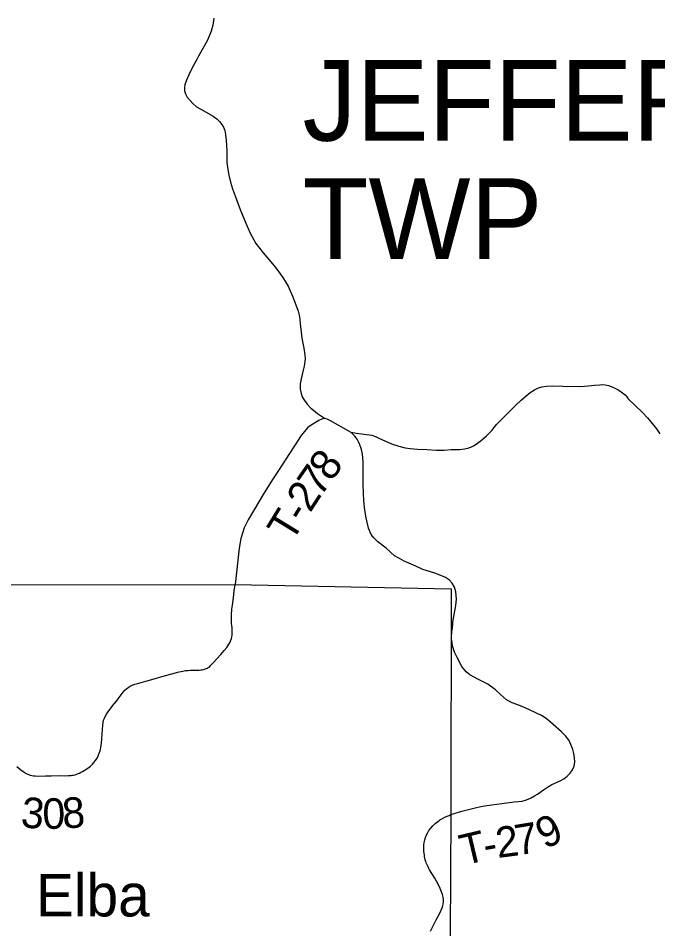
# Model space of a CAD drawing. Extents: x -10.5 to 40.6, y -3.2 to 22.
# Drawn here: x -9.045 to -7.857, y 17.758 to 19.45 of the extents above; entities that cross this region are included whole.
import ezdxf

# ---------------------------------------------------------------- set-up
doc = ezdxf.new("R2010")
doc.units = 0
for name, color, linetype in [('GM_X_Township_Road', 7, 'Continuous'), ('GM_X_Township_Road_Text', 7, 'Continuous'), ('GM_X_Township_Text', 7, 'Continuous'), ('GM_X_Unincorporated_Text', 7, 'Continuous')]:
    doc.layers.add(name, color=color, linetype=linetype)

msp = doc.modelspace()

# ---------------------------------------------------------------- linework, layer by layer
at = {"layer": 'GM_X_Township_Road'}
for points in [[(-8.6812, 19.45), (-8.6832, 19.4369), (-8.6862, 19.4259), (-8.6897, 19.4164), (-8.6939, 19.4076), (-8.7095, 19.3795), (-8.7125, 19.3745), (-8.7227, 19.3552), (-8.728, 19.3443), (-8.7323, 19.3345), (-8.735, 19.3258), (-8.7357, 19.3209), (-8.7357, 19.3151), (-8.734, 19.3092), (-8.7307, 19.3032), (-8.7252, 19.2969), (-8.7202, 19.2912), (-8.7134, 19.2854), (-8.7057, 19.2808), (-8.6823, 19.2675), (-8.6756, 19.2626), (-8.6705, 19.2577), (-8.6663, 19.2525), (-8.6633, 19.2474), (-8.6609, 19.2409), (-8.6594, 19.2337), (-8.6584, 19.223), (-8.6573, 19.203), (-8.657, 19.1814), (-8.6555, 19.1684), (-8.6537, 19.1583), (-8.6502, 19.1454), (-8.6465, 19.1327), (-8.6413, 19.118), (-8.6369, 19.1058), (-8.6325, 19.0943), (-8.622, 19.0687), (-8.6141, 19.0501), (-8.6031, 19.0313), (-8.5896, 19.0138), (-8.5721, 18.9933), (-8.5659, 18.986), (-8.5529, 18.9682), (-8.5435, 18.9519), (-8.5351, 18.9331), (-8.531, 18.9224), (-8.5246, 18.9051), (-8.5227, 18.8981), (-8.5214, 18.8902), (-8.5209, 18.8821), (-8.5194, 18.8661), (-8.5178, 18.8551), (-8.5141, 18.8364), (-8.5122, 18.8244), (-8.5119, 18.8168), (-8.5138, 18.8033), (-8.5155, 18.7958), (-8.5193, 18.7794), (-8.5207, 18.7702), (-8.5211, 18.7653), (-8.5212, 18.7605), (-8.5193, 18.7526), (-8.517, 18.7461), (-8.5129, 18.7394), (-8.5079, 18.7325), (-8.5012, 18.7254), (-8.4964, 18.7211), (-8.4887, 18.7154), (-8.4815, 18.7103), (-8.4756, 18.7067), (-8.4713, 18.705), (-8.465, 18.702), (-8.4266, 18.6803), (-8.4192, 18.679), (-8.4171, 18.6787)], [(-8.4171, 18.6787), (-8.4119, 18.6781), (-8.3979, 18.6762), (-8.3877, 18.6748), (-8.3814, 18.6724), (-8.3749, 18.6693), (-8.3516, 18.659), (-8.3376, 18.6542), (-8.3257, 18.6512), (-8.3167, 18.65), (-8.3034, 18.6491), (-8.2859, 18.6484), (-8.2677, 18.6468), (-8.2538, 18.647), (-8.2403, 18.648), (-8.2249, 18.6486), (-8.2157, 18.6496), (-8.2097, 18.6509), (-8.2039, 18.6528), (-8.1981, 18.656), (-8.1915, 18.6602), (-8.1844, 18.6658), (-8.175, 18.6737), (-8.1699, 18.6785), (-8.1648, 18.6839), (-8.1561, 18.6945), (-8.1473, 18.7039), (-8.1353, 18.716), (-8.1205, 18.7305), (-8.1104, 18.7399), (-8.1015, 18.748), (-8.0937, 18.7542), (-8.0859, 18.7591), (-8.0787, 18.7628), (-8.0713, 18.7648), (-8.0635, 18.7662), (-8.0521, 18.7669), (-8.0334, 18.7659), (-8.0003, 18.7653), (-7.9854, 18.7668), (-7.9745, 18.768), (-7.9642, 18.7687), (-7.959, 18.7691), (-7.9545, 18.7686), (-7.9487, 18.7671), (-7.9406, 18.7643), (-7.9341, 18.7611), (-7.929, 18.7584), (-7.9221, 18.7538), (-7.9175, 18.7497), (-7.9143, 18.7463), (-7.9116, 18.7425), (-7.8855, 18.7171), (-7.8762, 18.7074), (-7.8695, 18.6996), (-7.8593, 18.6868), (-7.8529, 18.6777)], [(-8.4756, 18.7067), (-8.4807, 18.7049), (-8.4861, 18.7022), (-8.5007, 18.6937), (-8.5065, 18.6893), (-8.5107, 18.6849), (-8.5193, 18.6745), (-8.5614, 18.6094), (-8.5711, 18.5947), (-8.588, 18.5678), (-8.6177, 18.5176), (-8.6247, 18.5029), (-8.6282, 18.4929), (-8.6309, 18.4831), (-8.6343, 18.4649), (-8.6419, 18.3972)], [(-8.2409, 17.9698), (-8.2208, 17.9762), (-8.1959, 17.9825), (-8.1852, 17.985), (-8.1743, 17.9867), (-8.1464, 17.9903), (-8.1234, 17.9933), (-8.1158, 17.994), (-8.1086, 17.9948), (-8.1009, 17.9971), (-8.0935, 18.0003), (-8.0859, 18.0045), (-8.0801, 18.008), (-8.0694, 18.0156), (-8.0617, 18.0206), (-8.0536, 18.0256), (-8.0382, 18.0327), (-8.0315, 18.0365), (-8.0251, 18.041), (-8.0194, 18.047), (-8.015, 18.0532), (-8.0123, 18.0601), (-8.011, 18.0679), (-8.0115, 18.0753), (-8.0127, 18.0831), (-8.0148, 18.0908), (-8.0169, 18.097), (-8.0216, 18.1077), (-8.0283, 18.116), (-8.0359, 18.1236), (-8.0511, 18.1374), (-8.0613, 18.1459), (-8.0662, 18.1497), (-8.0731, 18.1537), (-8.0823, 18.1586), (-8.0964, 18.1653), (-8.1118, 18.1718), (-8.1271, 18.1775), (-8.1376, 18.1832), (-8.1491, 18.1928), (-8.1584, 18.2017), (-8.1725, 18.2121), (-8.1908, 18.2212), (-8.2059, 18.2295), (-8.2128, 18.235), (-8.2206, 18.245), (-8.2297, 18.262), (-8.2343, 18.2716), (-8.2378, 18.2833), (-8.239, 18.2894), (-8.2395, 18.2926), (-8.2397, 18.2956), (-8.2398, 18.2987), (-8.2397, 18.3019), (-8.2395, 18.3058), (-8.2391, 18.3095), (-8.2388, 18.3132), (-8.2384, 18.317), (-8.2381, 18.3196), (-8.2377, 18.3222), (-8.2375, 18.3244), (-8.2372, 18.3266), (-8.2368, 18.3309), (-8.2322, 18.3584), (-8.2309, 18.3703), (-8.2317, 18.3837), (-8.2341, 18.3926), (-8.2386, 18.3999), (-8.2437, 18.4057), (-8.251, 18.4105), (-8.2595, 18.4143), (-8.271, 18.4182), (-8.2929, 18.4255), (-8.3063, 18.4314), (-8.3279, 18.4408), (-8.3366, 18.4456), (-8.3459, 18.4507), (-8.3615, 18.4648), (-8.3768, 18.4768), (-8.3845, 18.4839), (-8.3894, 18.4901), (-8.3944, 18.5023), (-8.3983, 18.5214), (-8.4009, 18.5354), (-8.4028, 18.5527), (-8.4039, 18.5825), (-8.4041, 18.6259), (-8.4053, 18.6396), (-8.4068, 18.648), (-8.4101, 18.6572), (-8.4124, 18.6625), (-8.4154, 18.6672), (-8.4193, 18.673), (-8.4223, 18.6764), (-8.4266, 18.6803)], [(-9.0472, 18.0594), (-9.0434, 18.0561), (-9.0397, 18.053), (-9.0336, 18.0484), (-9.0299, 18.0462), (-9.0266, 18.0447), (-9.0225, 18.0433), (-9.0195, 18.0425), (-9.0163, 18.042), (-9.0134, 18.0417), (-9.0072, 18.0415), (-8.9942, 18.0417), (-8.9837, 18.0419), (-8.9688, 18.0422), (-8.9588, 18.0421), (-8.9514, 18.0422), (-8.9488, 18.0423), (-8.9464, 18.0425), (-8.9441, 18.0429), (-8.942, 18.0432), (-8.9388, 18.044), (-8.9357, 18.0451), (-8.9333, 18.0461), (-8.9309, 18.047), (-8.9282, 18.0485), (-8.9251, 18.0502), (-8.9223, 18.0519), (-8.9155, 18.0563), (-8.9106, 18.0601), (-8.9069, 18.0634), (-8.9039, 18.0666), (-8.9008, 18.0705), (-8.8981, 18.0747), (-8.8959, 18.0791), (-8.894, 18.0837), (-8.8926, 18.0884), (-8.8912, 18.0945), (-8.89, 18.1025), (-8.8892, 18.1105), (-8.8883, 18.1279), (-8.8877, 18.136), (-8.887, 18.1409), (-8.886, 18.1451), (-8.8845, 18.1492), (-8.8826, 18.1531), (-8.8801, 18.1574), (-8.8758, 18.1635), (-8.8692, 18.1718), (-8.8619, 18.1809), (-8.8588, 18.1848), (-8.8495, 18.1972), (-8.8463, 18.201), (-8.8436, 18.2036), (-8.8402, 18.2063), (-8.837, 18.2082), (-8.8331, 18.2101), (-8.8279, 18.2121), (-8.8208, 18.2143), (-8.8076, 18.2178), (-8.7962, 18.2208), (-8.7711, 18.2282), (-8.7592, 18.2316), (-8.746, 18.235), (-8.742, 18.236), (-8.7387, 18.2366), (-8.7362, 18.237), (-8.7338, 18.2374), (-8.7313, 18.2377), (-8.7288, 18.2379), (-8.7251, 18.2382), (-8.7208, 18.2383), (-8.7083, 18.2385), (-8.7054, 18.2387), (-8.7028, 18.2389), (-8.7006, 18.2393), (-8.6985, 18.2398), (-8.6965, 18.2404), (-8.6949, 18.2411), (-8.693, 18.242), (-8.6916, 18.243), (-8.6903, 18.244), (-8.6889, 18.2453), (-8.6876, 18.2466), (-8.6825, 18.252), (-8.6681, 18.2675), (-8.662, 18.2746), (-8.6574, 18.2804), (-8.6532, 18.2866), (-8.6511, 18.2904), (-8.6495, 18.2937), (-8.6483, 18.2973), (-8.6477, 18.3003), (-8.6473, 18.3025), (-8.6471, 18.305), (-8.647, 18.3068), (-8.647, 18.3099), (-8.6471, 18.313), (-8.6475, 18.3173), (-8.6479, 18.3209), (-8.6483, 18.3255), (-8.6484, 18.3301), (-8.6486, 18.3357), (-8.6484, 18.3413), (-8.6476, 18.3518), (-8.6469, 18.3592), (-8.645, 18.3733), (-8.6442, 18.3788), (-8.6433, 18.3855), (-8.6419, 18.3972)], [(-8.2788, 17.7532), (-8.2763, 17.7584), (-8.2722, 17.7671), (-8.2687, 17.7741), (-8.2625, 17.7856), (-8.259, 17.7922), (-8.257, 17.7967), (-8.2559, 17.8003), (-8.2552, 17.8039), (-8.2548, 17.8076), (-8.255, 17.812), (-8.2555, 17.8163), (-8.2567, 17.8211), (-8.2584, 17.8265), (-8.2607, 17.8322), (-8.2641, 17.8393), (-8.268, 17.8463), (-8.2712, 17.8516), (-8.2807, 17.867), (-8.2821, 17.8695), (-8.2836, 17.8725), (-8.2848, 17.8751), (-8.2859, 17.8775), (-8.2868, 17.8799), (-8.2878, 17.8829), (-8.2886, 17.8859), (-8.2893, 17.8888), (-8.2898, 17.8917), (-8.2904, 17.8949), (-8.2912, 17.9011), (-8.2915, 17.9073), (-8.2913, 17.9128), (-8.2907, 17.9177), (-8.2897, 17.9226), (-8.2883, 17.9273), (-8.2864, 17.9319), (-8.2842, 17.9363), (-8.2819, 17.94), (-8.2785, 17.9445), (-8.2745, 17.9491), (-8.2705, 17.953), (-8.2662, 17.9566), (-8.2616, 17.9598), (-8.2568, 17.9627), (-8.2522, 17.965), (-8.248, 17.9669), (-8.2445, 17.9684), (-8.2409, 17.9698)]]:
    msp.add_lwpolyline(points, dxfattribs=at)
at = {"layer": 'GM_X_Township_Text'}
msp.add_lwpolyline([(-10.5445, 19.4241), (-9.8621, 19.4152), (-9.3297, 19.4093), (-9.2736, 19.4089), (-9.2734, 18.9532), (-9.2666, 18.9242), (-9.2573, 18.7823), (-9.2552, 18.7211), (-9.2586, 18.705), (-9.2677, 18.6789), (-9.2756, 18.3974), (-9.1719, 18.3965), (-8.6421, 18.3977), (-8.2403, 18.3894), (-8.2411, 17.9704), (-8.2441, 17.4134), (-7.9861, 17.4086), (-7.6509, 17.4026), (-7.3241, 17.3974), (-6.9004, 17.4016), (-6.4692, 17.3961), (-6.192, 17.3965), (-6.1874, 16.891), (-6.062, 16.8858)], dxfattribs=at)

# ---------------------------------------------------------------- texts
at = {"layer": 'GM_X_Township_Road_Text'}
for s, rotation, p in [('8', 53.4465, (-8.4638, 18.5868)), ('7', 55.2361, (-8.4835, 18.5584)), ('2', 56.9046, (-8.5024, 18.5295)), ('T', 58.5166, (-8.5367, 18.4738)), ('-', 58.0964, (-8.5145, 18.5099)), ('3', 354.2629, (-9.0412, 17.9468)), ('0', 1.047, (-8.9991, 17.943)), ('8', 3.7012, (-8.9612, 17.9438)), ('7', 9.2522, (-8.1176, 17.8938)), ('9', 25.6282, (-8.0662, 17.9048)), ('T', 13.3939, (-8.2169, 17.8752)), ('2', 7.4891, (-8.1542, 17.889)), ('-', 10.5353, (-8.1763, 17.8849))]:
    msp.add_text(s, height=0.0568, rotation=rotation, dxfattribs=at).set_placement(p)
at = {"layer": 'GM_X_Township_Text'}
for s, p in [('JEFFERSON', (-8.5166, 19.2221)), ('TWP', (-8.5166, 19.0021))]:
    msp.add_text(s, height=0.15, rotation=0, dxfattribs=at).set_placement(p)
at = {"layer": 'GM_X_Unincorporated_Text'}
msp.add_text('Elba', height=0.07898, rotation=0, dxfattribs=at).set_placement((-9.0117, 17.7806))

doc.saveas('drawing.dxf')
